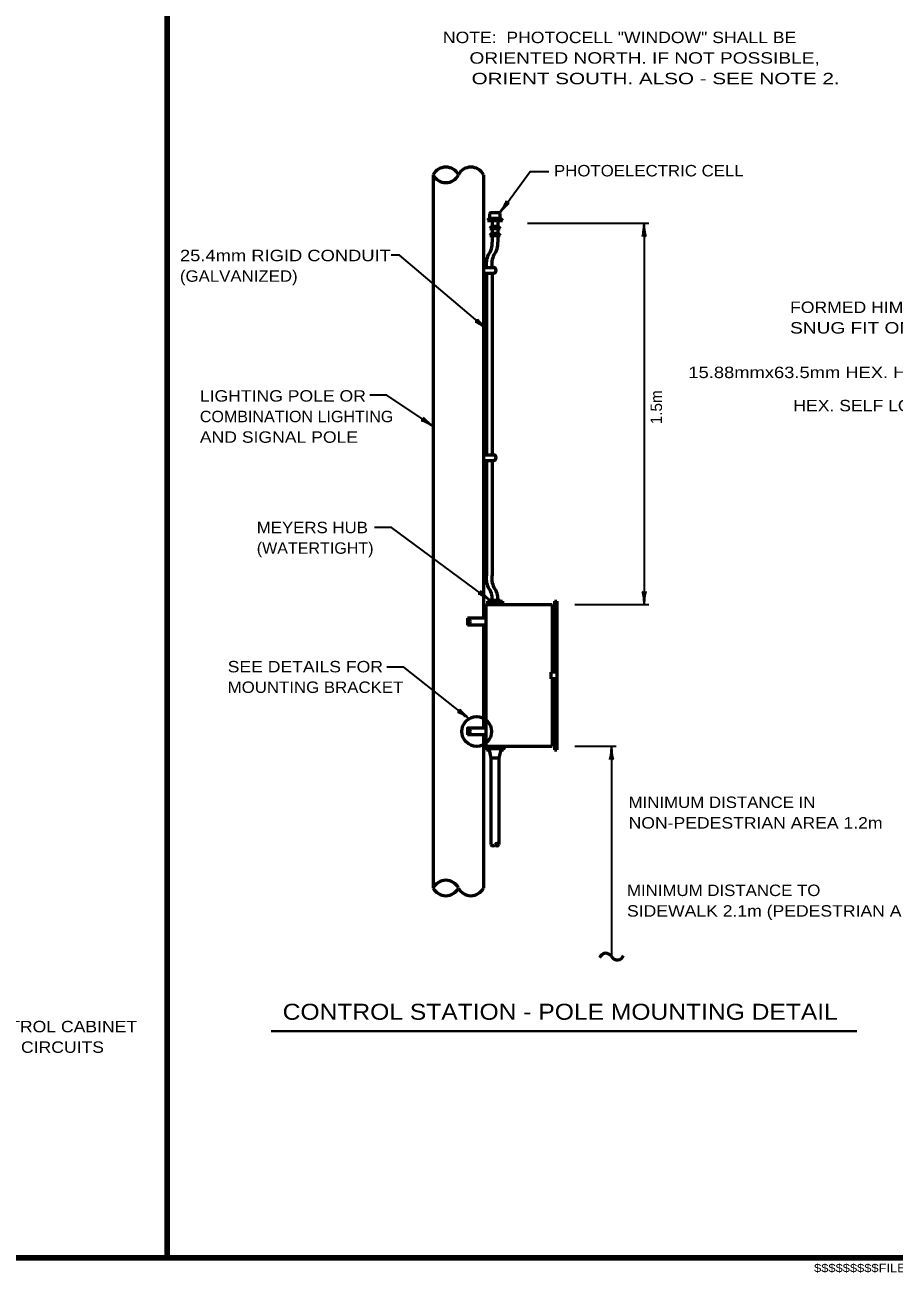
# Model space of a CAD drawing. Extents: x -33 to 680, y -7 to 447.
# Drawn here: x 274.7 to 464.8, y -0.4 to 272.6 of the extents above; entities that cross this region are included whole.
import ezdxf

# ---------------------------------------------------------------- set-up
doc = ezdxf.new("R2010")
doc.units = 0
doc.layers.add('1', color=7, linetype='Continuous', lineweight=53)

msp = doc.modelspace()

# ---------------------------------------------------------------- linework, layer by layer
at = {"layer": '1', "lineweight": 106}
msp.add_line((305.763, 289.208), (305.763, 2.994), dxfattribs=at)
at = {"layer": '1'}
for p, q in [((363.968, 239.862), (363.968, 83.862)), ((374.968, 239.862), (374.968, 142.862)), ((376.343, 230.362), (375.843, 229.862)), ((375.843, 229.862), (379.093, 229.862)), ((376.343, 230.362), (376.343, 231.362)), ((376.343, 230.362), (378.593, 230.362)), ((376.593, 231.612), (378.343, 231.612)), ((376.843, 229.862), (376.843, 228.612)), ((378.093, 229.862), (378.093, 228.612)), ((378.593, 230.362), (378.593, 231.362)), ((378.593, 230.362), (379.093, 229.862)), ((376.843, 228.612), (376.343, 228.112)), ((376.343, 228.112), (378.593, 228.112)), ((376.843, 227.112), (376.343, 226.612)), ((376.343, 226.612), (378.593, 226.612)), ((376.843, 228.612), (378.093, 228.612)), ((376.843, 228.112), (376.843, 227.112)), ((376.843, 227.112), (378.093, 227.112)), ((376.843, 226.612), (376.843, 225.112)), ((378.093, 228.612), (378.593, 228.112)), ((378.093, 228.112), (378.093, 227.112)), ((378.093, 227.112), (378.593, 226.612)), ((378.093, 226.612), (378.093, 225.112)), ((374.968, 219.612), (377.218, 219.612)), ((374.968, 218.362), (377.218, 218.362)), ((375.593, 218.362), (375.593, 178.612)), ((376.843, 218.362), (376.843, 178.612)), ((374.968, 178.612), (377.218, 178.612)), ((374.968, 177.362), (377.218, 177.362)), ((375.593, 177.362), (375.593, 152.362)), ((376.843, 177.362), (376.843, 152.362)), ((375.468, 145.862), (389.968, 145.862)), ((375.468, 145.862), (375.468, 114.362)), ((375.843, 146.612), (379.093, 146.612)), ((375.843, 146.612), (375.843, 145.862)), ((376.343, 146.862), (378.593, 146.862)), ((376.343, 146.862), (376.343, 146.612)), ((378.593, 146.862), (378.593, 146.612)), ((379.093, 146.612), (379.093, 145.862)), ((389.968, 145.862), (389.968, 131.112)), ((390.468, 146.612), (390.968, 146.612)), ((390.468, 146.612), (390.468, 131.112)), ((390.968, 146.612), (390.968, 114.112)), ((375.468, 142.862), (371.468, 142.862)), ((371.468, 142.862), (371.468, 141.362)), ((375.468, 141.362), (371.468, 141.362)), ((374.968, 141.362), (374.968, 118.862)), ((390.968, 131.112), (389.718, 131.112)), ((389.718, 131.112), (389.718, 129.612)), ((390.968, 129.612), (389.718, 129.612)), ((389.968, 129.612), (389.968, 114.862)), ((390.468, 129.612), (390.468, 114.112)), ((375.468, 117.362), (371.468, 117.362)), ((374.968, 117.362), (374.968, 83.862)), ((375.468, 114.862), (389.968, 114.862)), ((379.469, 114.862), (379.469, 114.362)), ((375.468, 114.362), (379.469, 114.362)), ((375.593, 114.362), (375.593, 114.112)), ((375.593, 114.112), (376.093, 114.112)), ((376.093, 114.362), (376.093, 114.112)), ((376.093, 114.362), (376.593, 112.362)), ((376.593, 112.362), (378.344, 112.362)), ((376.593, 112.362), (376.593, 93.362)), ((378.844, 114.362), (378.344, 112.362)), ((378.344, 112.362), (378.344, 93.362)), ((378.844, 114.362), (378.844, 114.112)), ((378.844, 114.112), (379.344, 114.112)), ((379.344, 114.362), (379.344, 114.112)), ((390.468, 114.112), (390.968, 114.112))]:
    msp.add_line(p, q, dxfattribs=at)
at = {"layer": '1', "lineweight": 35}
for p, q in [((411.093, 229.237), (384.593, 229.237)), ((410.093, 229.237), (410.093, 145.862)), ((394.968, 145.862), (411.093, 145.862)), ((394.968, 114.862), (403.968, 114.862)), ((402.968, 114.862), (402.968, 68.862))]:
    msp.add_line(p, q, dxfattribs=at)
at = {"layer": '1', "lineweight": 40}
msp.add_line((328.555, 52.559), (456.585, 52.559), dxfattribs=at)
at = {"layer": '1', "lineweight": 158}
msp.add_line((674.767, 2.994), (15.1, 2.994), dxfattribs=at)
at = {"layer": '1', "lineweight": 35}
for points in [[(378.572, 231.612), (385.18, 240.579), (389.236, 240.579)], [(375.593, 206.158), (356.554, 222.273), (354.738, 222.273)], [(363.968, 184.866), (353.788, 191.655), (350.1, 191.655)], [(376.343, 146.862), (354.825, 162.749), (351.138, 162.749)], [(371.799, 120.892), (357.54, 132.165), (353.853, 132.165)]]:
    msp.add_lwpolyline(points, dxfattribs=at)
at = {"layer": '1'}
msp.add_lwpolyline([(375.468, 118.862), (371.468, 118.862), (371.468, 117.362)], dxfattribs=at)
for centre, radius in [((371.966, 142.506), 0.125), ((371.978, 141.722), 0.125), ((373.469, 118.104), 3.25), ((371.966, 118.506), 0.125), ((371.978, 117.722), 0.125)]:
    msp.add_circle(centre, radius, dxfattribs=at)
for centre, radius, start, end in [((366.718, 238.466), 3.084, 26.91799, 153.08201), ((372.218, 238.466), 3.084, 26.91799, 153.08201), ((366.718, 241.248), 3.084, 206.91799, 333.08201), ((376.593, 231.362), 0.25, 90, 180), ((378.343, 231.362), 0.25, 0, 90), ((372.913, 224.818), 3.941, 321.34618, 4.26992), ((374.163, 224.818), 3.941, 321.34618, 4.26992), ((380.386, 220.319), 4.845, 155.12469, 188.3921), ((381.157, 220.388), 4.383, 153.31278, 190.204), ((377.053, 218.987), 0.646, 284.81519, 75.18481), ((377.053, 177.987), 0.646, 284.81519, 75.18481), ((380.386, 151.655), 4.845, 171.6079, 204.87531), ((381.157, 151.585), 4.383, 169.796, 206.68722), ((372.913, 147.155), 3.941, 355.73008, 38.65382), ((374.163, 147.155), 3.941, 355.73008, 38.65382), ((377.031, 93.627), 0.512, 211.1809, 328.8191), ((377.906, 93.083), 0.512, 31.1809, 148.8191), ((377.906, 93.627), 0.512, 211.1809, 328.8191), ((366.718, 82.475), 3.084, 26.91799, 153.08201), ((366.718, 85.258), 3.084, 206.91799, 333.08201), ((372.218, 85.258), 3.084, 206.91799, 333.08201), ((401.721, 68.148), 1.437, 29.80152, 162.19848), ((404.215, 69.576), 1.437, 209.80152, 342.19848)]:
    msp.add_arc(centre, radius, start, end, dxfattribs=at)
at = {"layer": '1', "lineweight": 40}
for centre, major_axis, ratio, start_param, end_param in [((378.997, 232.654), (-0.934, -1.53), 0.122415, 0.8963533, 3.1415927), ((379.407, 232.388), (1.183, 1.31), 0.07063, 6.2823074, 8.5597026), ((409.881, 228.116), (0.176, 1.756), 0.07063, 3.1407148, 5.41811), ((410.369, 228.146), (-0.156, 1.786), 0.122415, 0.8963533, 3.1415927), ((374.582, 206.652), (1.464, -1.034), 0.122415, 0.8963533, 3.1415927), ((374.582, 206.652), (1.464, -1.034), 0.122415, 0.8963533, 3.1415927), ((374.875, 207.043), (-1.227, 1.269), 0.07063, 6.2823074, 8.5597026), ((374.875, 207.043), (-1.227, 1.269), 0.07063, 6.2823074, 8.5597026), ((362.907, 185.242), (1.572, -0.861), 0.122415, 0.8963533, 3.1415927), ((362.907, 185.242), (1.572, -0.861), 0.122415, 0.8963533, 3.1415927), ((363.153, 185.664), (-1.364, 1.121), 0.07063, 6.2823074, 8.5597026), ((363.153, 185.664), (-1.364, 1.121), 0.07063, 6.2823074, 8.5597026), ((375.301, 147.288), (1.529, -0.935), 0.122415, 0.8963533, 3.1415927), ((375.567, 147.698), (-1.309, 1.185), 0.07063, 6.2823074, 8.5597026), ((409.817, 146.953), (0.156, -1.786), 0.122415, 0.8963533, 3.1415927), ((410.305, 146.982), (-0.176, -1.756), 0.07063, 3.1407148, 5.41811), ((371.052, 121.753), (1.269, -1.227), 0.07063, 3.1407148, 5.41811), ((370.772, 121.352), (1.498, -0.985), 0.122415, 0.8963533, 3.1415927), ((402.756, 113.741), (0.176, 1.756), 0.07063, 3.1407148, 5.41811), ((403.244, 113.771), (-0.156, 1.786), 0.122415, 0.8963533, 3.1415927)]:
    msp.add_ellipse(centre, major_axis=major_axis, ratio=ratio, start_param=start_param, end_param=end_param, dxfattribs=at)

# ---------------------------------------------------------------- texts
at = {"layer": '1'}
for s, height, width, p in [('NOTE:  PHOTOCELL "WINDOW" SHALL BE', 2.5, 1.15, (366.087, 268.68)), ('     ORIENTED NORTH. IF NOT POSSIBLE,', 2.5, 1.25, (366.087, 264.18)), ('     ORIENT SOUTH. ALSO - SEE NOTE 2.', 2.5, 1.35, (366.087, 259.68)), ('PHOTOELECTRIC CELL', 2.5, 1.1, (390.383, 239.524)), ('25.4mm RIGID CONDUIT', 2.5, 1.2, (308.567, 220.974)), ('(GALVANIZED)', 2.5, 1.1, (308.567, 216.474)), ('FORMED HIMGE TO BE', 2.5, 1.15, (442.014, 209.644)), ('SNUG FIT ON 15.88mm BOLT.', 2.5, 1.25, (442.014, 205.144)), ('15.88mmx63.5mm HEX. HEAD MACHINE BOLT', 2.5, 1.2, (419.77, 195.401)), ('LIGHTING POLE OR', 2.5, 1.15, (312.923, 190.256)), ('HEX. SELF LOCKING NUT', 2.5, 1.15, (442.734, 188.143)), ('COMBINATION LIGHTING', 2.5, 1.05, (312.923, 185.756)), ('AND SIGNAL POLE', 2.5, 1.15, (312.923, 181.256)), ('MEYERS HUB', 2.5, 1.1, (325.372, 161.476)), ('(WATERTIGHT)', 2.5, 1.05, (325.372, 156.976)), ('SEE DETAILS FOR', 2.5, 1.15, (319.009, 131.035)), ('MOUNTING BRACKET', 2.5, 1.1, (319.009, 126.535)), ('MINIMUM DISTANCE IN', 2.5, 1.1, (406.7, 101.368)), ('NON-PEDESTRIAN AREA 1.2m', 2.5, 1.15, (406.7, 96.868)), ('MINIMUM DISTANCE TO', 2.5, 1.1, (406.353, 82.107)), ('SIDEWALK 2.1m (PEDESTRIAN AREA)', 2.5, 1.15, (406.353, 77.607)), ('CONTROL STATION - POLE MOUNTING DETAIL', 3.5, 1.15, (331.039, 55.044)), ('TO CONTROL CABINET, OR IF CONTROL CABINET', 2.5, 1.15, (206.29, 52.306)), ('IS ON SERVICE POLE, TO LIGHTING CIRCUITS', 2.5, 1.15, (206.29, 47.806)), ('$$$$$$$$$FILENAME$$$$$$$$', 1.833, 1.15, (447.267, -0.172))]:
    msp.add_text(s, height=height, dxfattribs=dict(at, width=width)).set_placement(p)
msp.add_text('1.5m', height=2.5, rotation=90, dxfattribs=at).set_placement((414.007, 185.303))

doc.saveas('drawing.dxf')
